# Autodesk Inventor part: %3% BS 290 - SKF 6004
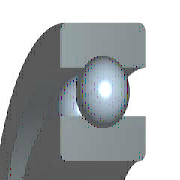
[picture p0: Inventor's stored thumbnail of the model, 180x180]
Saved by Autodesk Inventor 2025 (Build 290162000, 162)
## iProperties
Created: 2024-01
Part Number: %3% BS 290 - SKF 6004
Material: Acciaio, Dolce
Description: Cuscinetti a sfere a fila singola
Document SubType Name: Modeling
Standard: BS 290
Designer: R5800u
Standards Organization: BSI
Language: it-IT
Size Designation: SKF 6004
Categories: <MemberInstance><Categories><Category DisplayName="Parti albero" InternalName="7f7aeb1f-a693-4053-b835-cee3144e0d98" Mnemonic="SHFT"><Category DisplayName="Cusc
Density: 7.85 g/cm^3
Appearance: Semilucidato
IsCustomPart: 0
Author: R5800u
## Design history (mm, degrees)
node "WorkPoint1"
node "WorkAxis1"
node "WorkPlane3"
node "WorkPlane4"
node "WorkPoint2"
pattern_circular "Seriepolare1" dims "d17" = 74.45455 (= msp_pocet), angle "d19" = 360 deg
body "Solid1"
node "Schizzo1"
revolve "Rivoluzione1" stored, may be unused: angle "d6" = 360 deg
revolve "Rivoluzione2" stored, may be unused: angle "d10" = 360 deg
node "Schizzo4"
revolve "Rivoluzione3" stored, may be unused: angle "d16" = 360 deg
fillet "Raccordo1" dims "d20" = 0.6 (= r)
sketch "Schizzo2"
  geometry: L1 (10, 12)-(21, 12); L2 (10, 0)-(10, 12); L3 (21, 0)-(10, 0); L4 (21, 12)-(21, 0); L5 (0, 0)-(0, 20); L6 (0, 0)-(0, 20); L7 (-7.2, 0)-(43.2, 0) reference
  constraints: 12 end point, 3 vertical, 2 horizontal, 1 collinear, 1 other
  dimensions: "d1" = 20 diameter of L1.start L5 (= Diam); "d3" = 42 diameter of L1.end L5 (= DD); "d5" = 12 distance of L2.start L1.start (= msp_mdtd2)
sketch "Schizzo3"
  geometry: L1 (17.48, 12)-(17.48, 8.64); L2 (13.52, 12)-(17.48, 12); L3 (13.52, 8.64)-(13.52, 12); L4 (13.52, 0)-(13.52, 3.36); L5 (17.48, 0)-(13.52, 0); L6 (17.48, 3.36)-(17.48, 0); L7 (21, 0)-(-21, 0) reference; L8 (21, 12)-(-21, 12) reference; L9 (0, -42.29)-(0, 61.29); L10 (0, 82.007)-(0, -63.007) reference; A1 r 3.3 centre (15.5, 6) between (17.48, 3.36) and (17.48, 8.64); A2 r 3.3 centre (15.5, 6) between (13.52, 8.64) and (13.52, 3.36)
  constraints: 14 end point, 4 collinear, 4 point on circle, 4 vertical, 2 centre point, 2 concentric, 2 horizontal, 2 point on line
  dimensions: "d9" = 6.6 diameter of A1 (= msp_mdtd6); "d21" = 13.52 distance between parallel lines of L9 L4 (= 0.5 x msp_d1); "d22" = 15.5 distance from line of L9 A1.centre (= 0.5 x msp_ds); "d23" = 17.48 distance between parallel lines of L9 L6 (= 0.5 x msp_dd1)
sketch "Schizzo5"
  geometry: L1 (15.5, 2.7)-(15.5, 9.3); L2 (17.48, 0)-(-17.48, 0) reference; L3 (15.5, 2.7)-(15.5, 9.3); A1 r 3.3 centre (15.5, 6) between (15.5, 2.7) and (15.5, 9.3); A2 r 3.3 centre (15.5, 6) between (17.48, 3.36) and (17.48, 8.64) reference
  constraints: 4 end point, 2 point on circle, 1 centre point, 1 concentric, 1 vertical
  dimensions: "d13" = 0 horizontal distance of A1.centre L1.start; "d15" = 6.6001 diameter of A1 (computed from msp_mdtd6)
other parameters: "Diam" = 20 [user parameter; used in 3 equation terms], "DD" = 42 [user parameter; used in 3 equation terms], "B" = 12 [user parameter; used in 1 equation term], "r" = 0.6 [user parameter; used in 1 equation term], "msp_ds" = 31 (= 0.5 x Diam + 0.5 x DD) [user parameter; used in 5 equation terms], "msp_d0" = 6.6 (= -0.3 x Diam + 0.3 x DD) [user parameter; used in 4 equation terms], "msp_d1" = 27.04 (= msp_ds - 0.6 x msp_d0) [user parameter; used in 1 equation term], "msp_dd1" = 34.96 (= msp_ds + 0.6 x msp_d0) [user parameter; used in 1 equation term], "msp_pom" = 46.5 (= 1.5 x msp_ds) [user parameter; used in 1 equation term], "msp_mdtd2" = 12 (= B) [user parameter; used in 3 equation terms], "msp_mdtd4" = 31 (= msp_ds) [user parameter], "msp_mdtd6" = 6.6 (= msp_d0) [user parameter; used in 2 equation terms], "msp_mdtd7" = 6 (= 0.5 x msp_mdtd2) [user parameter], "msp_pocet" = 74.45455 (computed from msp_d0, msp_pom) [user parameter; used in 1 equation term], "d2" = 72 (derived), "d4" = 19 (derived), "d7" = 0, "d8" = 15.6 (derived), "d11" = -12 (computed from msp_mdtd2), "d12" = 0 (derived), "d14" = 15.6001 (derived), "d26" = 0, "d27" = 0, "d28" = 0, "d29" = 0, "d30" = 0
